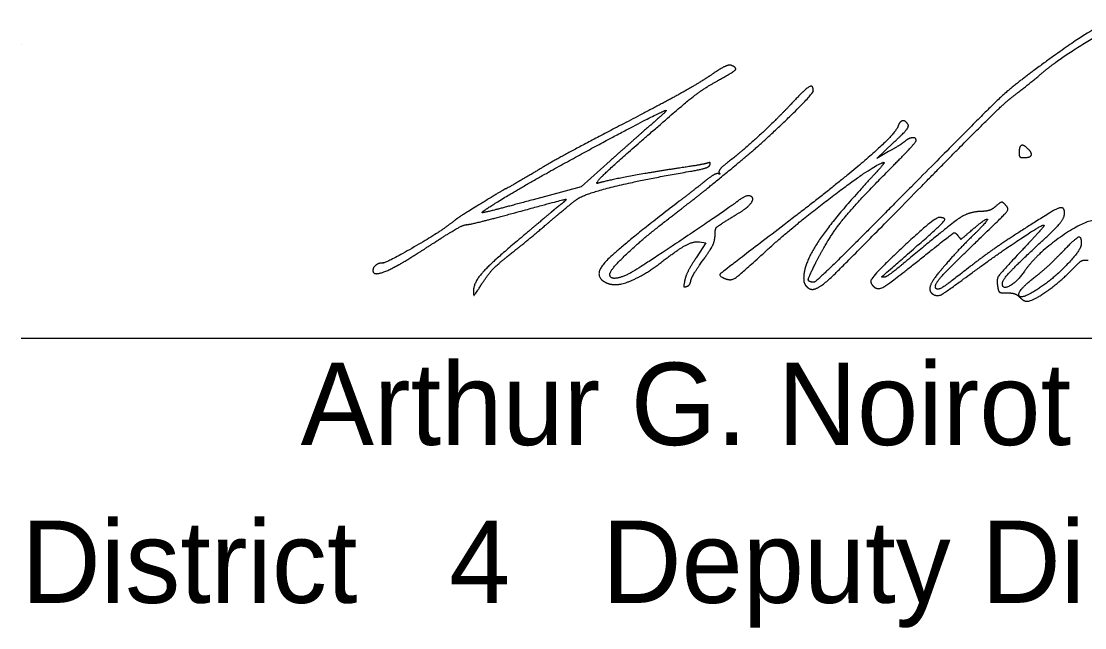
# Model space of a CAD drawing. Extents: x 0 to 34, y 0 to 22.
# Drawn here: x 24.5 to 26.309, y 8.324 to 9.355 of the extents above; entities that cross this region are included whole.
import ezdxf

# ---------------------------------------------------------------- set-up
doc = ezdxf.new("R2010")
doc.units = 0
doc.layers.add('SH_Data', color=7, linetype='Continuous')
doc.layers.add('SH_Text', color=7, linetype='Continuous')

msp = doc.modelspace()

# ---------------------------------------------------------------- linework, layer by layer
at = {"layer": 'SH_Data'}
for p, q in [((24.5, 9.316), (24.5, 9.316)), ((24.5, 8.816), (28, 8.816))]:
    msp.add_line(p, q, dxfattribs=at)
at = {"layer": 'SH_Text'}
for points in [[(25.9757, 9.1333), (25.9553, 9.1218), (25.9835, 9.1481)], [(25.5019, 9.1176), (25.4524, 9.0735), (25.3709, 9.0515)], [(25.6541, 8.9798), (25.6648, 8.9785), (25.648, 8.9527)]]:
    msp.add_lwpolyline(points, dxfattribs=at)
for points in [[(26.3721, 9.3549), (26.3508, 9.3557), (26.2942, 9.324), (26.2228, 9.2713)], [(26.2446, 9.2734), (26.262, 9.288), (26.3372, 9.3358), (26.3575, 9.345)], [(25.7076, 9.2801), (25.704, 9.2815), (25.6884, 9.2737), (25.6701, 9.2613)], [(25.6863, 9.2547), (25.7116, 9.2687), (25.7179, 9.2762), (25.7076, 9.2801)], [(26.2228, 9.2713), (26.1844, 9.243), (26.144, 9.2047), (26.0143, 9.0737)], [(26.1824, 9.2234), (26.2048, 9.2408), (26.2318, 9.2625), (26.2446, 9.2734)], [(25.6701, 9.2613), (25.6528, 9.2497), (25.6018, 9.221), (25.5568, 9.1975)], [(25.5639, 9.1593), (25.6286, 9.2157), (25.6606, 9.2406), (25.6863, 9.2547)], [(25.7228, 9.1164), (25.7606, 9.1476), (25.8474, 9.2315), (25.8474, 9.2369)], [(25.8474, 9.2369), (25.8474, 9.2477), (25.8328, 9.2388), (25.8096, 9.2141)], [(25.8096, 9.2141), (25.7844, 9.1871), (25.7285, 9.1357), (25.6999, 9.1133)], [(26.0303, 9.0731), (26.1029, 9.1472), (26.1713, 9.2148), (26.1824, 9.2234)], [(25.5568, 9.1975), (25.4808, 9.158), (25.4017, 9.1156), (25.3873, 9.1068)], [(25.3933, 9.0964), (25.4703, 9.1392), (25.5958, 9.2051), (25.5974, 9.2035)], [(25.5974, 9.2035), (25.5979, 9.2029), (25.5878, 9.1933), (25.5749, 9.1821)], [(25.5749, 9.1821), (25.562, 9.1709), (25.5291, 9.1419), (25.5019, 9.1176)], [(25.9919, 9.177), (25.9867, 9.1628), (25.8928, 9.0815), (25.7981, 9.0091)], [(25.9835, 9.1481), (26.0011, 9.1645), (26.0106, 9.1763), (26.0087, 9.1793)], [(26.0087, 9.1793), (26.0043, 9.1865), (25.9949, 9.1852), (25.9919, 9.177)], [(25.4819, 9.0797), (25.4734, 9.077), (25.5091, 9.1116), (25.5639, 9.1593)], [(26.0225, 9.1522), (26.0225, 9.1575), (26.0096, 9.1563), (26.0025, 9.1502)], [(25.9745, 9.1003), (26.0009, 9.1269), (26.0225, 9.1502), (26.0225, 9.1522)], [(26.0025, 9.1502), (25.9989, 9.1472), (25.9869, 9.1396), (25.9757, 9.1333)], [(26.2127, 9.1382), (26.2053, 9.1456), (26.1976, 9.1419), (26.1976, 9.131)], [(26.2055, 9.1231), (26.2164, 9.1231), (26.2201, 9.1308), (26.2127, 9.1382)], [(26.1976, 9.131), (26.1976, 9.1259), (26.2004, 9.1231), (26.2055, 9.1231)], [(25.3873, 9.1068), (25.3704, 9.0963), (25.3253, 9.0701), (25.3243, 9.0701)], [(25.6172, 9.105), (25.5738, 9.0985), (25.4937, 9.0836), (25.4819, 9.0797)], [(25.6031, 9.0207), (25.6421, 9.0506), (25.6697, 9.0727), (25.7228, 9.1164)], [(25.6657, 9.1134), (25.6615, 9.1121), (25.6397, 9.1083), (25.6172, 9.105)], [(25.6385, 9.0999), (25.6565, 9.103), (25.6705, 9.1075), (25.6715, 9.1105)], [(25.6715, 9.1105), (25.6727, 9.1141), (25.6708, 9.115), (25.6657, 9.1134)], [(25.6999, 9.1133), (25.6916, 9.1068), (25.686, 9.0996), (25.6874, 9.0974)], [(25.7655, 8.963), (25.8167, 9.0099), (25.9567, 9.1149), (25.968, 9.1149)], [(25.968, 9.1149), (25.9692, 9.1149), (25.9571, 9.1007), (25.9411, 9.0834)], [(25.2845, 9.0294), (25.2801, 9.0294), (25.3464, 9.0702), (25.3933, 9.0964)], [(25.4464, 9.053), (25.4582, 9.0616), (25.5634, 9.0872), (25.6385, 9.0999)], [(25.686, 9.0957), (25.6839, 9.097), (25.6731, 9.0909), (25.662, 9.082)], [(25.6874, 9.0974), (25.6888, 9.0952), (25.6882, 9.0944), (25.686, 9.0957)], [(25.9411, 9.0834), (25.8821, 9.0195), (25.8311, 8.943), (25.8311, 8.9184)], [(25.853, 8.9469), (25.8726, 8.9859), (25.9184, 9.0437), (25.9745, 9.1003)], [(25.3243, 9.0701), (25.3237, 9.0701), (25.3134, 9.0641), (25.3013, 9.0567)], [(25.662, 9.082), (25.6509, 9.0732), (25.6317, 9.0583), (25.6194, 9.0488)], [(25.846, 8.8991), (25.8564, 8.8991), (25.9018, 8.9421), (26.0303, 9.0731)], [(26.0143, 9.0737), (25.9259, 8.9843), (25.8513, 8.9112), (25.8487, 8.9113)], [(25.3013, 9.0567), (25.25, 9.0252), (25.2425, 9.0203), (25.2263, 9.0079)], [(25.3709, 9.0515), (25.3261, 9.0394), (25.2872, 9.0294), (25.2845, 9.0294)], [(25.3397, 9.0294), (25.4205, 9.0513), (25.4308, 9.0532), (25.4179, 9.0434)], [(25.398, 9.0134), (25.4179, 9.0304), (25.4397, 9.0482), (25.4464, 9.053)], [(25.6194, 9.0488), (25.5146, 8.9685), (25.4724, 8.9225), (25.4932, 8.9114)], [(25.7204, 9.0502), (25.7018, 9.0358), (25.5479, 8.9328), (25.5351, 8.9262)], [(25.7365, 9.0402), (25.7491, 9.0525), (25.7349, 9.0614), (25.7204, 9.0502)], [(26.1768, 9.0401), (26.1706, 9.0475), (26.1652, 9.0472), (26.156, 9.0388)], [(25.257, 9.0091), (25.2612, 9.0091), (25.2984, 9.0182), (25.3397, 9.0294)], [(25.4016, 9.0302), (25.3971, 9.0264), (25.3712, 9.0045), (25.344, 8.9816)], [(25.4179, 9.0434), (25.4134, 9.04), (25.4061, 9.0341), (25.4016, 9.0302)], [(25.7059, 9.0198), (25.7199, 9.0283), (25.7337, 9.0374), (25.7365, 9.0402)], [(26.1333, 9.0316), (26.1127, 9.0312), (26.0812, 9.0102), (26.0005, 8.9429)], [(26.2501, 9.0294), (26.1942, 8.9945), (26.1409, 8.9586), (26.1144, 8.9378)], [(26.1292, 8.9841), (26.1712, 9.0246), (26.1806, 9.0355), (26.1768, 9.0401)], [(26.156, 9.0388), (26.1518, 9.0351), (26.1416, 9.0318), (26.1333, 9.0316)], [(26.2364, 8.9809), (26.2597, 9.0024), (26.2748, 9.0211), (26.2749, 9.0285)], [(26.2749, 9.0285), (26.275, 9.0378), (26.2642, 9.0382), (26.2501, 9.0294)], [(25.3431, 8.9679), (25.3534, 8.976), (25.3782, 8.9965), (25.398, 9.0134)], [(25.5013, 8.9246), (25.5013, 8.9324), (25.5595, 8.9873), (25.6031, 9.0207)], [(25.6805, 8.9943), (25.6805, 9.0023), (25.6857, 9.0076), (25.7059, 9.0198)], [(26.0608, 9.0213), (26.0537, 9.0213), (25.9452, 8.9199), (25.9452, 8.9132)], [(26.0279, 8.9764), (26.0659, 9.0096), (26.0744, 9.0213), (26.0608, 9.0213)], [(26.1124, 8.9958), (26.1386, 9.0186), (26.1476, 9.0187), (26.1243, 8.9959)], [(26.3343, 9.0156), (26.3182, 9.0218), (26.2295, 8.9622), (26.2068, 8.9301)], [(25.2263, 9.0079), (25.207, 8.9932), (25.1211, 8.9439), (25.1147, 8.9439)], [(25.2024, 8.9785), (25.2282, 8.9953), (25.2528, 9.0091), (25.257, 9.0091)], [(25.6541, 8.9404), (25.6726, 8.9663), (25.6805, 8.9824), (25.6805, 8.9943)], [(25.7981, 9.0091), (25.6927, 8.9286), (25.6856, 8.922), (25.6985, 8.917)], [(26.0369, 8.9564), (26.083, 8.9932), (26.0889, 8.9967), (26.0934, 8.9906)], [(26.1243, 8.9959), (26.1029, 8.9749), (26.0798, 8.9499), (26.0602, 8.9265)], [(26.0934, 8.9906), (26.098, 8.9842), (26.0996, 8.9847), (26.1124, 8.9958)], [(26.1176, 8.9273), (26.1614, 8.9595), (26.2383, 9.0105), (26.2402, 9.0084)], [(26.2402, 9.0084), (26.241, 9.0077), (26.2243, 8.9887), (26.2032, 8.9663)], [(25.1364, 8.9378), (25.1469, 8.9433), (25.1766, 8.9616), (25.2024, 8.9785)], [(25.344, 8.9816), (25.2986, 8.9434), (25.2693, 8.91), (25.2693, 8.8964)], [(25.5868, 8.9436), (25.6174, 8.9671), (25.6435, 8.9811), (25.6541, 8.9798)], [(25.9679, 8.9196), (25.9632, 8.9197), (25.9646, 8.9211), (26.0279, 8.9764)], [(26.0563, 8.9006), (26.0518, 8.9051), (26.0767, 8.9337), (26.1292, 8.9841)], [(26.1691, 8.9092), (26.1691, 8.9148), (26.1975, 8.9451), (26.2364, 8.9809)], [(26.3034, 8.9763), (26.3034, 8.9668), (26.257, 8.9178), (26.2326, 8.9016)], [(26.2683, 8.96), (26.2933, 8.9857), (26.3034, 8.9904), (26.3034, 8.9763)], [(25.2836, 8.9083), (25.2957, 8.927), (25.3134, 8.9446), (25.3431, 8.9679)], [(25.6985, 8.917), (25.7078, 8.9135), (25.7223, 8.9234), (25.7655, 8.963)], [(25.9498, 8.9043), (25.957, 8.897), (25.9788, 8.9101), (26.0369, 8.9564)], [(26.2032, 8.9663), (26.1656, 8.9264), (26.1587, 8.9155), (26.1617, 8.9005)], [(26.225, 8.9204), (26.2357, 8.9286), (26.2552, 8.9464), (26.2683, 8.96)], [(25.1147, 8.9439), (25.1077, 8.9439), (25.0983, 8.9364), (25.0983, 8.9309)], [(25.5118, 8.9073), (25.5243, 8.9073), (25.5656, 8.9273), (25.5868, 8.9436)], [(25.648, 8.9527), (25.6388, 8.9384), (25.6301, 8.9212), (25.6288, 8.9145)], [(25.6392, 8.9137), (25.64, 8.918), (25.6467, 8.93), (25.6541, 8.9404)], [(25.8487, 8.9113), (25.8384, 8.9115), (25.8395, 8.9201), (25.853, 8.9469)], [(26.0005, 8.9429), (25.985, 8.93), (25.9704, 8.9196), (25.9679, 8.9196)], [(26.2866, 8.9316), (26.3001, 8.9454), (26.3071, 8.9496), (26.3151, 8.9487)], [(25.0983, 8.9309), (25.0983, 8.9244), (25.1179, 8.9279), (25.1364, 8.9378)], [(25.5351, 8.9262), (25.5197, 8.9183), (25.5013, 8.9174), (25.5013, 8.9246)], [(26.0602, 8.9265), (26.0484, 8.9123), (26.0441, 8.8953), (26.0512, 8.8909)], [(26.0512, 8.8909), (26.0585, 8.8864), (26.0729, 8.8943), (26.1176, 8.9273)], [(26.1144, 8.9378), (26.0764, 8.9082), (26.0595, 8.8974), (26.0563, 8.9006)], [(26.2068, 8.9301), (26.194, 8.9118), (26.1691, 8.8981), (26.1691, 8.9092)], [(26.2326, 8.9016), (26.2008, 8.8804), (26.1942, 8.8968), (26.225, 8.9204)], [(26.2113, 8.8788), (26.2203, 8.8788), (26.2672, 8.9116), (26.2866, 8.9316)], [(25.2693, 8.8964), (25.2693, 8.8879), (25.2715, 8.8898), (25.2836, 8.9083)], [(25.4932, 8.9114), (25.4974, 8.9091), (25.5057, 8.9073), (25.5118, 8.9073)], [(25.6288, 8.9145), (25.6269, 8.905), (25.6276, 8.9026), (25.632, 8.904)], [(25.632, 8.904), (25.6352, 8.9051), (25.6384, 8.9094), (25.6392, 8.9137)], [(25.8311, 8.9184), (25.8311, 8.9132), (25.8333, 8.9067), (25.836, 8.904)], [(25.836, 8.904), (25.8387, 8.9013), (25.8432, 8.8991), (25.846, 8.8991)], [(25.9452, 8.9132), (25.9452, 8.9108), (25.9472, 8.9068), (25.9498, 8.9043)], [(26.1617, 8.9005), (26.1628, 8.895), (26.1668, 8.8931), (26.1772, 8.8931)], [(26.1772, 8.8931), (26.1853, 8.8932), (26.1943, 8.8902), (26.1985, 8.886)], [(26.1985, 8.886), (26.2025, 8.882), (26.2082, 8.8788), (26.2113, 8.8788)]]:
    msp.add_open_spline(points, degree=2, dxfattribs=at)

# ---------------------------------------------------------------- texts
for s, p in [('Arthur G. Noirot Jr., P.E.', (24.9752, 8.6344)), ('District   4   Deputy Director', (24.5, 8.366))]:
    msp.add_text(s, height=0.14, dxfattribs=at).set_placement(p)

doc.saveas('drawing.dxf')
